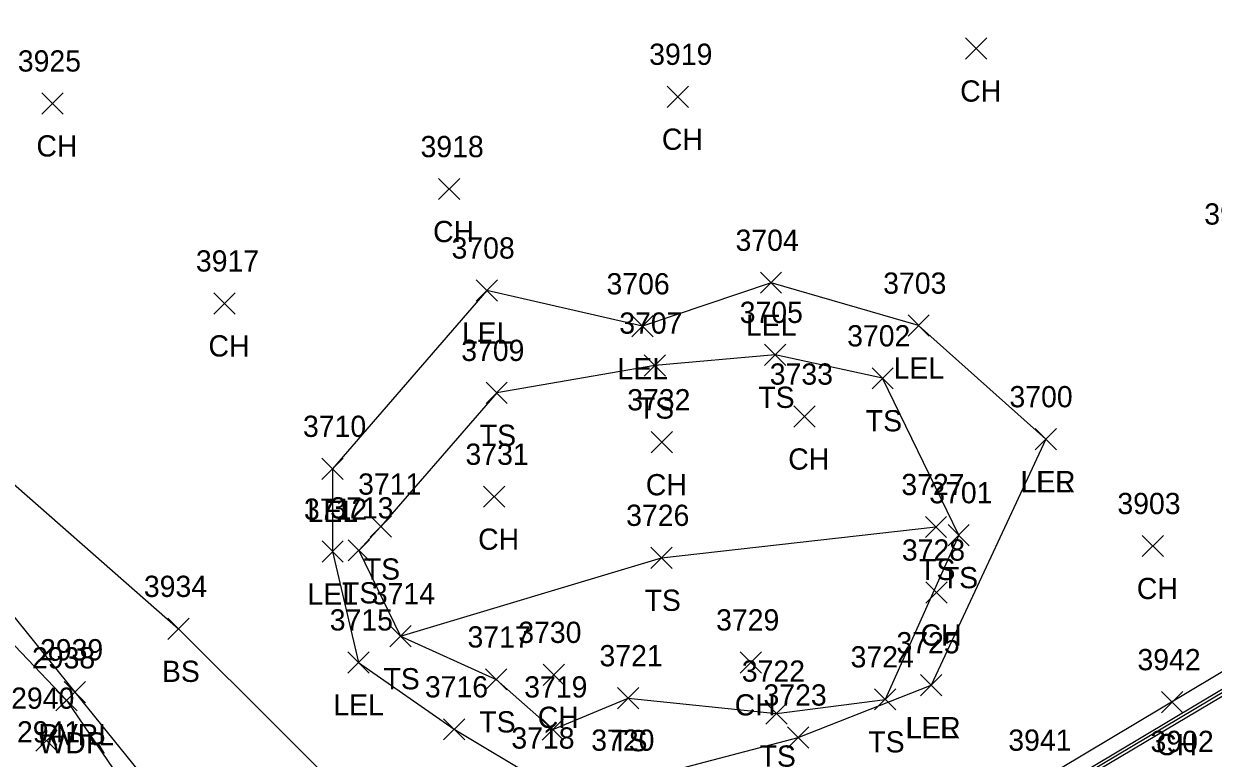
# Model space of a CAD drawing. Extents: x 1443590 to 1445966, y 578314 to 580556.
# Drawn here: x 1444183.6 to 1444295.6, y 578996.5 to 579065.6 of the extents above; entities that cross this region are included whole.
import ezdxf

# ---------------------------------------------------------------- set-up
doc = ezdxf.new("R2010")
doc.units = 0
for name, color, linetype in [('BB', 7, 'Continuous'), ('BDC', 7, 'Continuous'), ('BELB', 7, 'Continuous'), ('BF', 7, 'Continuous'), ('L_A', 7, 'Continuous'), ('L_I', 7, 'Continuous'), ('L_TIC', 7, 'Continuous'), ('LARO', 7, 'Continuous'), ('LAWA', 7, 'Continuous'), ('LAWE', 7, 'Continuous'), ('LELB', 7, 'Continuous')]:
    doc.layers.add(name, color=color, linetype=linetype)

msp = doc.modelspace()

# ---------------------------------------------------------------- linework, layer by layer
at = {"layer": 'BB'}
msp.add_lwpolyline([(1444269.39, 578986.22), (1444329.38, 579021.84)], dxfattribs=at)
at = {"layer": 'BDC'}
msp.add_lwpolyline([(1444393.51, 579062.49), (1444394.12, 579061.31), (1444330.7, 579023.4), (1444267.08, 578985.39), (1444205.13, 578948.27), (1444203.4, 578948.67), (1444203.22, 578948.84)], dxfattribs=at)
at = {"layer": 'BELB'}
msp.add_lwpolyline([(1444394.46, 579061.26), (1444330.85, 579023.12), (1444267.26, 578985.21), (1444204.09, 578947.49)], dxfattribs=at)
at = {"layer": 'BF'}
msp.add_lwpolyline([(1444393.51, 579062.49), (1444330.04, 579024.65), (1444266.43, 578986.63), (1444203.22, 578948.84)], dxfattribs=at)
at = {"layer": 'L_TIC'}
for points in [[(1444272.3, 579062.28), (1444274.3, 579064.28)], [(1444274.3, 579062.28), (1444272.3, 579064.28)], [(1444185.32, 579057.11), (1444187.32, 579059.11)], [(1444187.32, 579057.11), (1444185.32, 579059.11)], [(1444244.21, 579057.74), (1444246.21, 579059.74)], [(1444246.21, 579057.74), (1444244.21, 579059.74)], [(1444222.67, 579049.05), (1444224.67, 579051.05)], [(1444224.67, 579049.05), (1444222.67, 579051.05)], [(1444252.98, 579040.23), (1444254.98, 579042.23)], [(1444254.98, 579040.23), (1444252.98, 579042.23)], [(1444226.23, 579039.5), (1444228.23, 579041.5)], [(1444228.23, 579039.5), (1444226.23, 579041.5)], [(1444201.53, 579038.28), (1444203.53, 579040.28)], [(1444203.53, 579038.28), (1444201.53, 579040.28)], [(1444240.88, 579036.13), (1444242.88, 579038.13)], [(1444242.88, 579036.13), (1444240.88, 579038.13)], [(1444266.88, 579036.19), (1444268.88, 579038.19)], [(1444268.88, 579036.19), (1444266.88, 579038.19)], [(1444253.37, 579033.44), (1444255.37, 579035.44)], [(1444255.37, 579033.44), (1444253.37, 579035.44)], [(1444242.03, 579032.43), (1444244.03, 579034.43)], [(1444244.03, 579032.43), (1444242.03, 579034.43)], [(1444263.49, 579031.23), (1444265.49, 579033.23)], [(1444265.49, 579031.23), (1444263.49, 579033.23)], [(1444227.15, 579029.86), (1444229.15, 579031.86)], [(1444229.15, 579029.86), (1444227.15, 579031.86)], [(1444256.12, 579027.63), (1444258.12, 579029.63)], [(1444258.12, 579027.63), (1444256.12, 579029.63)], [(1444278.86, 579025.5), (1444280.86, 579027.5)], [(1444280.86, 579025.5), (1444278.86, 579027.5)], [(1444278.86, 579025.5), (1444280.86, 579027.5)], [(1444280.86, 579025.5), (1444278.86, 579027.5)], [(1444242.7, 579025.21), (1444244.7, 579027.21)], [(1444244.7, 579025.21), (1444242.7, 579027.21)], [(1444211.69, 579022.71), (1444213.69, 579024.71)], [(1444213.69, 579022.71), (1444211.69, 579024.71)], [(1444226.91, 579020.08), (1444228.91, 579022.08)], [(1444228.91, 579020.08), (1444226.91, 579022.08)], [(1444216.23, 579017.27), (1444218.23, 579019.27)], [(1444218.23, 579017.27), (1444216.23, 579019.27)], [(1444268.51, 579017.23), (1444270.51, 579019.23)], [(1444270.51, 579017.23), (1444268.51, 579019.23)], [(1444270.65, 579016.46), (1444272.65, 579018.46)], [(1444272.65, 579016.46), (1444270.65, 579018.46)], [(1444270.65, 579016.46), (1444272.65, 579018.46)], [(1444272.65, 579016.46), (1444270.65, 579018.46)], [(1444288.93, 579015.44), (1444290.93, 579017.44)], [(1444290.93, 579015.44), (1444288.93, 579017.44)], [(1444211.7, 579014.91), (1444213.7, 579016.91)], [(1444213.7, 579014.91), (1444211.7, 579016.91)], [(1444214.17, 579015.03), (1444216.17, 579017.03)], [(1444216.17, 579015.03), (1444214.17, 579017.03)], [(1444242.66, 579014.33), (1444244.66, 579016.33)], [(1444244.66, 579014.33), (1444242.66, 579016.33)], [(1444268.56, 579011.06), (1444270.56, 579013.06)], [(1444270.56, 579011.06), (1444268.56, 579013.06)], [(1444197.19, 579007.64), (1444199.19, 579009.64)], [(1444199.19, 579007.64), (1444197.19, 579009.64)], [(1444218.08, 579006.94), (1444220.08, 579008.94)], [(1444220.08, 579006.94), (1444218.08, 579008.94)], [(1444218.08, 579006.94), (1444220.08, 579008.94)], [(1444220.08, 579006.94), (1444218.08, 579008.94)], [(1444214.13, 579004.48), (1444216.13, 579006.48)], [(1444216.13, 579004.48), (1444214.13, 579006.48)], [(1444251.07, 579004.48), (1444253.07, 579006.48)], [(1444253.07, 579004.48), (1444251.07, 579006.48)], [(1444232.53, 579003.31), (1444234.53, 579005.31)], [(1444234.53, 579003.31), (1444232.53, 579005.31)], [(1444227.1, 579002.88), (1444229.1, 579004.88)], [(1444229.1, 579002.88), (1444227.1, 579004.88)], [(1444268.05, 579002.33), (1444270.05, 579004.33)], [(1444270.05, 579002.33), (1444268.05, 579004.33)], [(1444268.05, 579002.33), (1444270.05, 579004.33)], [(1444270.05, 579002.33), (1444268.05, 579004.33)], [(1444186.64, 579000.91), (1444188.64, 579002.91)], [(1444188.64, 579000.91), (1444186.64, 579002.91)], [(1444187.42, 579001.67), (1444189.42, 579003.67)], [(1444189.42, 579001.67), (1444187.42, 579003.67)], [(1444239.52, 579001.11), (1444241.52, 579003.11)], [(1444241.52, 579001.11), (1444239.52, 579003.11)], [(1444263.73, 579001), (1444265.73, 579003)], [(1444265.73, 579001), (1444263.73, 579003)], [(1444263.73, 579001), (1444265.73, 579003)], [(1444265.73, 579001), (1444263.73, 579003)], [(1444253.49, 578999.66), (1444255.49, 579001.66)], [(1444255.49, 578999.66), (1444253.49, 579001.66)], [(1444290.74, 579000.74), (1444292.74, 579002.74)], [(1444292.74, 579000.74), (1444290.74, 579002.74)], [(1444223.14, 578998.18), (1444225.14, 579000.18)], [(1444225.14, 578998.18), (1444223.14, 579000.18)], [(1444232.44, 578998.17), (1444234.44, 579000.17)], [(1444234.44, 578998.17), (1444232.44, 579000.17)], [(1444255.53, 578997.41), (1444257.53, 578999.41)], [(1444257.53, 578997.41), (1444255.53, 578999.41)], [(1444184.77, 578997.11), (1444186.77, 578999.11)], [(1444186.77, 578997.11), (1444184.77, 578999.11)]]:
    msp.add_lwpolyline(points, dxfattribs=at)
at = {"layer": 'LARO'}
for points in [[(1444279.86, 579026.5), (1444267.88, 579037.19), (1444253.98, 579041.23), (1444241.88, 579037.13), (1444227.23, 579040.5), (1444212.69, 579023.71), (1444212.7, 579015.91), (1444215.13, 579005.48), (1444224.14, 578999.18), (1444232.22, 578994.36), (1444240.4, 578994.16), (1444256.53, 578998.41), (1444269.05, 579003.33)], [(1444279.86, 579026.5), (1444269.05, 579003.33)]]:
    msp.add_lwpolyline(points, dxfattribs=at)
at = {"layer": 'LAWA'}
msp.add_lwpolyline([(1444164.59, 579023.19), (1444173.05, 579017.23), (1444187.64, 579001.91), (1444200.9, 578982.43)], dxfattribs=at)
at = {"layer": 'LAWE'}
msp.add_lwpolyline([(1444132.86, 579092.15), (1444138.96, 579083.21), (1444141.19, 579057.08), (1444148.07, 579045.28), (1444167.25, 579025.02), (1444174.77, 579019.56), (1444188.42, 579002.67), (1444202.86, 578984.81), (1444211.08, 578975.97), (1444218.07, 578968.05), (1444223.32, 578965.93), (1444225.77, 578959.78), (1444234.82, 578940.52), (1444239.56, 578925.63), (1444236.72, 578915.57)], dxfattribs=at)
at = {"layer": 'LELB'}
for points in [[(1444147.3, 579085.75), (1444154.3, 579067.94), (1444160.7, 579051.51), (1444170.69, 579032.78), (1444198.19, 579008.64), (1444217.42, 578989.47)], [(1444271.65, 579017.46), (1444264.49, 579032.23), (1444254.37, 579034.44), (1444243.03, 579033.43), (1444228.15, 579030.86), (1444217.23, 579018.27), (1444215.17, 579016.03), (1444219.08, 579007.94), (1444228.1, 579003.88), (1444233.44, 578999.17), (1444240.52, 579002.11), (1444254.49, 579000.66), (1444264.73, 579002)], [(1444219.08, 579007.94), (1444243.66, 579015.33), (1444269.51, 579018.23)], [(1444271.65, 579017.46), (1444264.73, 579002)]]:
    msp.add_lwpolyline(points, dxfattribs=at)

# ---------------------------------------------------------------- texts
at = {"layer": 'L_A'}
for s, p in [('CH', (1444271.79, 579058.28)), ('CH', (1444243.7, 579053.74)), ('CH', (1444184.81, 579053.11)), ('CH', (1444222.16, 579045.05)), ('LEL', (1444224.87, 579035.5)), ('LEL', (1444251.62, 579036.23)), ('CH', (1444201.01, 579034.28)), ('LEL', (1444239.52, 579032.13)), ('LEL', (1444265.52, 579032.19)), ('TS', (1444252.78, 579029.44)), ('TS', (1444241.44, 579028.43)), ('TS', (1444262.9, 579027.23)), ('TS', (1444226.56, 579025.86)), ('CH', (1444255.6, 579023.63)), ('CH', (1444242.19, 579021.21)), ('LER', (1444277.44, 579021.5)), ('LEL', (1444277.49, 579021.5)), ('LEL', (1444210.33, 579018.71)), ('CH', (1444226.4, 579016.08)), ('TS', (1444215.64, 579013.27)), ('TS', (1444267.92, 579013.23)), ('TS', (1444270.06, 579012.46)), ('TS', (1444270.06, 579012.46)), ('LEL', (1444210.33, 579010.91)), ('TS', (1444213.58, 579011.03)), ('CH', (1444288.42, 579011.44)), ('TS', (1444242.07, 579010.33)), ('CH', (1444268.05, 579007.06)), ('BS', (1444196.63, 579003.64)), ('TS', (1444217.49, 579002.94)), ('TS', (1444217.49, 579002.94)), ('LEL', (1444212.77, 579000.48)), ('CH', (1444250.56, 579000.48)), ('TS', (1444226.51, 578998.88)), ('CH', (1444232.01, 578999.31)), ('RVRL', (1444184.99, 578997.67)), ('LER', (1444266.63, 578998.33)), ('LEL', (1444266.69, 578998.33)), ('WDR', (1444185.01, 578996.91)), ('TS', (1444238.93, 578997.11)), ('TS', (1444263.14, 578997)), ('TS', (1444263.14, 578997)), ('CH', (1444290.23, 578996.74)), ('TS', (1444252.9, 578995.66))]:
    msp.add_text(s, height=2, dxfattribs=at).set_placement(p)
at = {"layer": 'L_I'}
for s, p in [('3919', (1444242.51, 579061.74)), ('3925', (1444183.06, 579061.11)), ('3918', (1444220.98, 579053.05)), ('3916', (1444294.77, 579046.7)), ('3708', (1444223.9, 579043.5)), ('3704', (1444250.64, 579044.23)), ('3917', (1444199.83, 579042.28)), ('3706', (1444238.49, 579040.13)), ('3703', (1444264.54, 579040.19)), ('3705', (1444251.03, 579037.44)), ('3707', (1444239.69, 579036.43)), ('3702', (1444261.15, 579035.23)), ('3709', (1444224.81, 579033.86)), ('3733', (1444253.86, 579031.63)), ('3732', (1444240.44, 579029.21)), ('3700', (1444276.43, 579029.5)), ('3700', (1444276.43, 579029.5)), ('3710', (1444209.91, 579026.71)), ('3731', (1444225.21, 579024.08)), ('3711', (1444215.1, 579021.27)), ('3727', (1444266.25, 579021.23)), ('3701', (1444268.88, 579020.46)), ('3701', (1444268.88, 579020.46)), ('3712', (1444210, 579018.91)), ('3713', (1444212.48, 579019.03)), ('3903', (1444286.59, 579019.44)), ('3726', (1444240.34, 579018.33)), ('3728', (1444266.3, 579015.06)), ('3934', (1444194.93, 579011.64)), ('3714', (1444216.39, 579010.94)), ('3714', (1444216.39, 579010.94)), ('3715', (1444212.43, 579008.48)), ('3729', (1444248.81, 579008.48)), ('3717', (1444225.4, 579006.88)), ('3730', (1444230.18, 579007.31)), ('3725', (1444265.79, 579006.33)), ('3725', (1444265.79, 579006.33)), ('2939', (1444185.15, 579005.67)), ('2938', (1444184.39, 579004.91)), ('3721', (1444237.83, 579005.11)), ('3724', (1444261.47, 579005)), ('3724', (1444261.47, 579005)), ('3942', (1444288.48, 579004.74)), ('3722', (1444251.23, 579003.66)), ('3716', (1444221.39, 579002.18)), ('3719', (1444230.74, 579002.17)), ('2940', (1444182.43, 579001.11)), ('3723', (1444253.27, 579001.41)), ('2941', (1444182.98, 578997.94)), ('3718', (1444229.53, 578997.36)), ('3720', (1444237.05, 578997.16)), ('3941', (1444276.32, 578997.16)), ('3902', (1444289.71, 578997.04))]:
    msp.add_text(s, height=2, dxfattribs=at).set_placement(p)

doc.saveas('drawing.dxf')
